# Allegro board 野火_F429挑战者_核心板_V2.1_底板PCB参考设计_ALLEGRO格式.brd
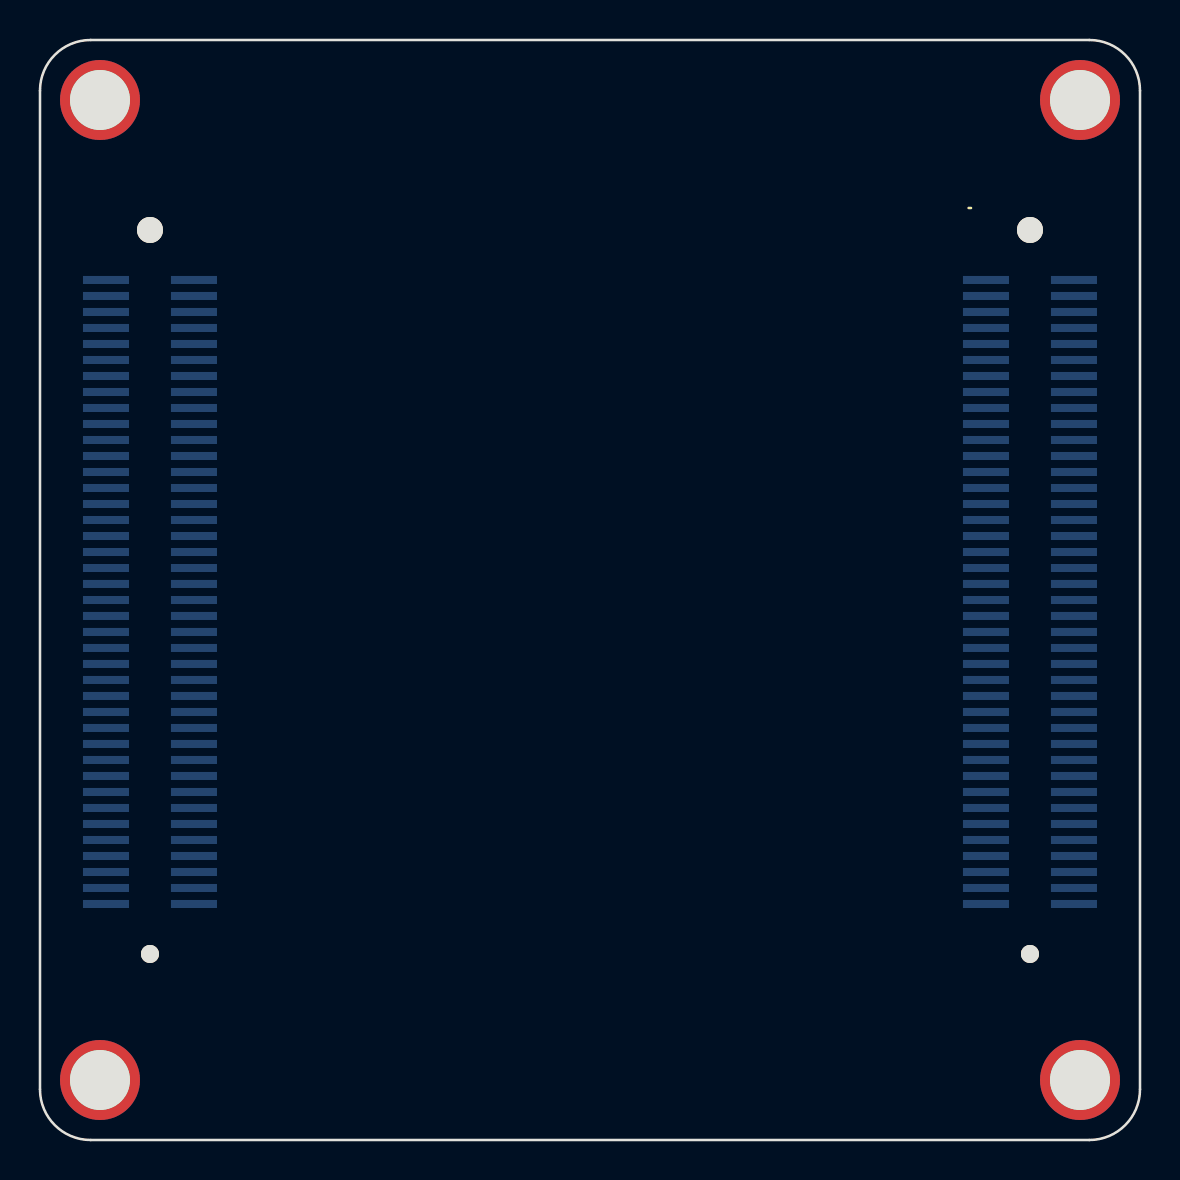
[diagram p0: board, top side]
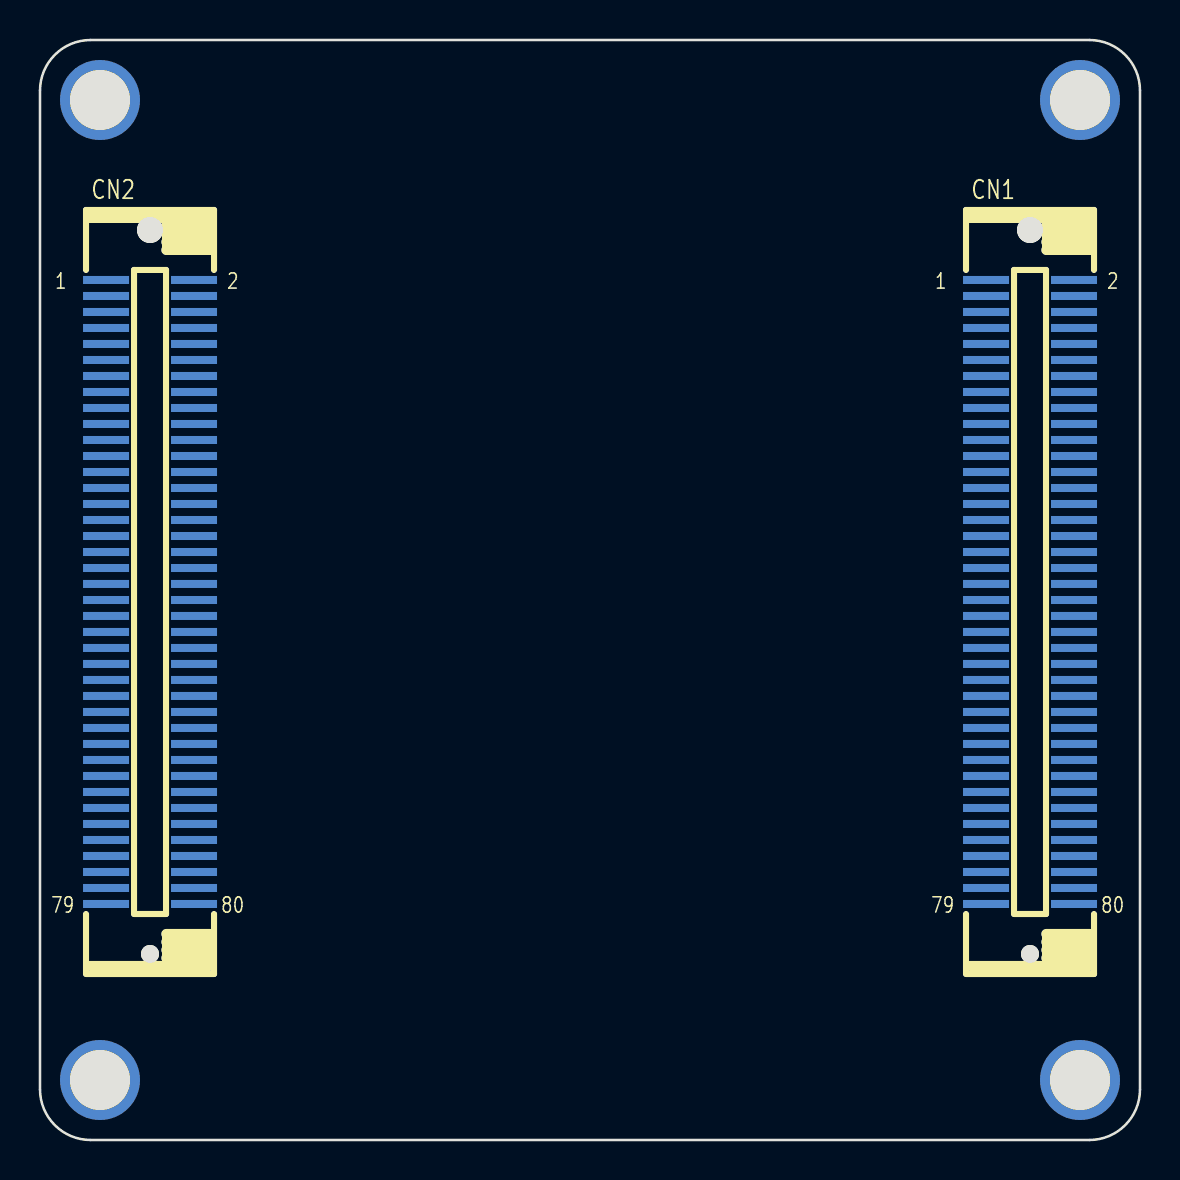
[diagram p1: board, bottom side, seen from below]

Outline 55 x 55 mm; copper layers: TOP, BOTTOM. Coordinates in mm from the lower left corner of the outline.
Outline path: 0,52.47 0,2.53 arc(0.74,0.74) 2.53,0 52.47,0 arc(54.26,0.74) 55,2.53 55,52.47 arc(54.26,54.26) 52.47,55 2.53,55 arc(0.74,54.26) 0,52.47

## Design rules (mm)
constraint set DEFAULT: min track width 0.127
net group DIFFPAIR0: nets PB14 PB15

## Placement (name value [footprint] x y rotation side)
CN1  B2BF_2X40_0P8  [B2BF-2X40-0P8]  5.5 27.4 180 bottom
CN2  B2BF_2X40_0P8  [B2BF-2X40-0P8]  49.5 27.4 180 bottom
H1  3.0mm  [T3]  3 3 270 top
H2  3.0mm  [T3]  52 3 0 top
H3  3.0mm  [T3]  52 52 90 top
H4  3.0mm  [T3]  3 52 180 top

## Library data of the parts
CN1 CN2 = B2BF_2X40_0
H1-H4 = SPACER_0

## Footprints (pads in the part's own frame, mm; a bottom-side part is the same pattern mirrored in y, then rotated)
B2BF-2X40-0P8
  round 0.899 hole 0.899 unplated: (0,-18.1)
  round 1.3 hole 1.3 unplated: (0,18.1)
  rect 2.301x0.401 smd: 1(-2.2,15.601) 2(2.2,15.601) 3(-2.2,14.801) 4(2.2,14.801) 5(-2.2,14) 6(2.2,14) 7(-2.2,13.2) 8(2.2,13.2) 9(-2.2,12.4) 10(2.2,12.4) 11(-2.2,11.6) 12(2.2,11.6) 13(-2.2,10.8) 14(2.2,10.8) 15(-2.2,10) 16(2.2,10) 17(-2.2,9.2) 18(2.2,9.2) 19(-2.2,8.4) 20(2.2,8.4) 21(-2.2,7.6) 22(2.2,7.6) 23(-2.2,6.8) 24(2.2,6.8) 25(-2.2,5.999) 26(2.2,5.999) 27(-2.2,5.199) 28(2.2,5.199) 29(-2.2,4.399) 30(2.2,4.399) 31(-2.2,3.599) 32(2.2,3.599) 33(-2.2,2.799) 34(2.2,2.799) 35(-2.2,1.999) 36(2.2,1.999) 37(-2.2,1.199) 38(2.2,1.199) 39(-2.2,0.401) 40(2.2,0.401) 41(-2.2,-0.401) 42(2.2,-0.401) 43(-2.2,-1.199) 44(2.2,-1.199) 45(-2.2,-1.999) 46(2.2,-1.999) 47(-2.2,-2.799) 48(2.2,-2.799) 49(-2.2,-3.599) 50(2.2,-3.599) 51(-2.2,-4.399) 52(2.2,-4.399) 53(-2.2,-5.199) 54(2.2,-5.199) 55(-2.2,-5.999) 56(2.2,-5.999) 57(-2.2,-6.8) 58(2.2,-6.8) 59(-2.2,-7.6) 60(2.2,-7.6) 61(-2.2,-8.4) 62(2.2,-8.4) 63(-2.2,-9.2) 64(2.2,-9.2) 65(-2.2,-10) 66(2.2,-10) 67(-2.2,-10.8) 68(2.2,-10.8) 69(-2.2,-11.6) 70(2.2,-11.6) 71(-2.2,-12.4) 72(2.2,-12.4) 73(-2.2,-13.2) 74(2.2,-13.2) 75(-2.2,-14) 76(2.2,-14) 77(-2.2,-14.801) 78(2.2,-14.801) 79(-2.2,-15.601) 80(2.2,-15.601)
T3
  round 4 hole 3: 1(0,0)

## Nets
5V: CN2.75 CN2.76 CN2.77 CN2.78 CN2.79 CN2.80
GND: CN1.9 CN1.39 CN1.40 CN1.79 CN2.3 CN2.4 CN2.11 CN2.12 CN2.17 CN2.23 CN2.24 CN2.50 CN2.71 CN2.72 CN2.73 H1.1(NC_1) H2.1(NC_1) H3.1(NC_1) H4.1(NC_1)
VBAT: CN2.74
BOOT0: CN2.54
NRST: CN2.10
PA0/WKUP: CN2.53
PA1: CN1.6
PA2: CN1.10
PA3: CN1.32
PA4: CN2.25
PA5: CN2.62
PA6: CN2.31
PA7: CN1.7
PA8: CN2.33
PA9: CN2.58
PA10: CN2.60
PA11: CN1.15
PA12: CN1.16
PA13: CN2.7
PA14: CN2.6
PA15: CN2.5
PB0: CN1.14
PB1: CN1.17
PB2: CN2.56
PB3: CN2.8
PB4: CN2.9
PB5: CN2.1
PB6: CN2.19
PB7: CN2.20
PB8: CN1.33
PB9: CN1.34
PB10: CN2.64
PB11: CN1.1
PB12: CN2.13
PB13: CN2.51
PB14: CN2.46
PB15: CN2.48
PC0: CN1.55
PC1: CN1.8
PC2: CN2.15
PC3: CN2.41
PC4: CN1.2
PC5: CN1.4
PC6: CN2.14
PC7: CN1.25
PC8: CN2.65
PC9: CN2.67
PC10: CN2.69
PC11: CN2.66
PC12: CN2.70
PC13/TAMPER: CN2.55
PD0: CN1.65
PD1: CN1.66
PD2: CN2.68
PD3: CN2.28
PD4: CN2.44
PD5: CN2.45
PD6: CN1.29
PD7: CN2.2
PD8: CN1.76
PD9: CN1.77
PD10: CN1.78
PD11: CN2.40
PD12: CN2.42
PD13: CN2.52
PD14: CN1.63
PD15: CN1.64
PE0: CN1.61
PE1: CN1.62
PE2: CN2.21
PE3: CN2.22
PE4: CN1.27
PE5: CN1.19
PE6: CN1.20
PE7: CN1.67
PE8: CN1.68
PE9: CN1.69
PE10: CN1.70
PE11: CN1.71
PE12: CN1.72
PE13: CN1.73
PE14: CN1.74
PE15: CN1.75
PF0: CN1.41
PF1: CN1.42
PF2: CN1.43
PF3: CN1.44
PF4: CN1.45
PF5: CN1.46
PF6: CN2.57
PF7: CN2.59
PF8: CN2.61
PF9: CN2.63
PF10: CN1.38
PF11: CN1.57
PF12: CN1.47
PF13: CN1.48
PF14: CN1.49
PF15: CN1.50
PG0: CN1.51
PG1: CN1.52
PG2: CN1.53
PG3: CN2.37
PG4: CN1.58
PG5: CN1.59
PG6: CN1.18
PG7: CN1.37
PG8: CN1.80
PG9: CN2.39
PG10: CN1.22
PG11: CN1.30
PG12: CN1.28
PG13: CN1.3
PG14: CN1.5
PG15: CN1.56
PH2: CN1.11
PH3: CN1.12
PH4: CN2.47
PH5: CN2.49
PH6: CN1.54
PH7: CN1.60
PH8: CN1.13
PH9: CN2.38
PH10: CN2.36
PH11: CN2.34
PH12: CN2.32
PH13: CN1.21
PH14: CN2.30
PH15: CN1.23
PI0: CN1.24
PI1: CN2.18
PI2: CN1.26
PI3: CN2.16
PI4: CN1.31
PI5: CN2.29
PI6: CN2.26
PI7: CN2.27
PI8: CN2.35
PI9: CN1.35
PI10: CN1.36
PI11: CN2.43
